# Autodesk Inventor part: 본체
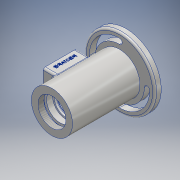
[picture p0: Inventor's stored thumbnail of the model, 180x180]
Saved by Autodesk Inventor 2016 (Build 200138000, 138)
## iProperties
Created: 2017-05
Part Number: 본체
Material: 알루미늄 6061
Document SubType Name: Modeling
Designer: USER
Density: 2.7 g/cm^3
Appearance: 알루미늄 - 평지
Mass: 673.236 g
Surface Area: 619.691 cm^2
Volume: 249.347 cm^3
Author: USER
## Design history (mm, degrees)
sketch "스케치1"
  geometry: C1 r 53 at (0, 0); 1 further point
  constraints: 1 centre point, 1 coincident
  dimensions: "d0" = 106 diameter of C1
extrude "돌출1" new body sketch "스케치1" distance "d1" = 10; taper "d2" = 0 deg
sketch "스케치2"
  geometry: C1 r 31 at (0, 0); 1 further point
  constraints: 1 centre point, 1 coincident
  dimensions: "d3" = 62 diameter of C1
extrude "돌출2" join sketch "스케치2" distance "d4" = 3; taper "d5" = 0 deg
sketch "스케치3"
  geometry: C1 r 31 at (0, 0); 1 further point
  constraints: 1 centre point, 1 coincident
  dimensions: "d6" = 62 diameter of C1
extrude "돌출3" join sketch "스케치3" distance "d7" = 102; taper "d8" = 0 deg
sketch "스케치4"
  geometry: L1 (0, 0)-(0, -177.717); L2 (-31, -112)-(31, -112) reference; L3 (-21, -112)-(-21, -103); L4 (-21, -103)-(-24, -103); L5 (-24, -103)-(-24, -100); L6 (-24, -100)-(-20, -100); L7 (-20, -100)-(-20, -91); L8 (-20, -91)-(-17.5, -91); L9 (-17.5, -91)-(-17.5, -87.75); L10 (-17.5, -87.75)-(-18.5, -87.75); L11 (-18.5, -87.75)-(-18.5, -86); L12 (-18.5, -86)-(-17.5, -86); L13 (31, 3)-(-31, 3) reference; L14 (-22.005, 3)-(-21.985, 3); L15 (-17.5, -75)-(-17.5, -86); L16 (0, 0)-(0, 7.987); L17 (-17.5, -75)-(-26, -75); L18 (-26, -75)-(-26, -37); L19 (-26, -37)-(-17.5, -37); L20 (-17.5, -37)-(-17.5, -26); L21 (-17.5, -26)-(-16.5, -26); L22 (-16.5, -26)-(-16.5, -21); L23 (-16.5, -21)-(-10, -21); L24 (-12.5, -11.7)-(-12.904, -11); L25 (-12.904, -11)-(-16, -11); L26 (-10, -21)-(-10, -18.3); L27 (-10, -18.3)-(-12.5, -18.3); L28 (-12.5, -18.3)-(-12.5, -11.7); L29 (-21, -112)-(0, -112); L30 (0, 3)-(-22, 3); L31 (0, -112)-(0, 3); L32 (-16, -11)-(-22, 3); 1 further point
  constraints: 60 end point, 14 perpendicular, 7 vertical, 6 point on line, 2 collinear, 2 horizontal, 2 midpoint, 1 horizontal alignment, 1 parallel
  dimensions: "d11" = 42 diameter of L3 L1; "d12" = 48 diameter of L5 L1; "d13" = 9 distance of L3.start L3.end; "d14" = 3 distance of L4.end L5.end; "d15" = 21 distance from line of L3.start L8; "d16" = 26 distance from line of L3.start L12; "d17" = 1.75 distance of L10.end L11.end; "d18" = 37 diameter of L11 L1; "d20" = 35 diameter of L9 L1; "d35" = 11 distance of L15.start L12.end; "d40" = 35 diameter of L15 L1; "d52" = 52 diameter of L18 L1; "d53" = 38 distance of L17.end L18.end; "d54" = 11 distance of L19.end L20.end; "d55" = 44 diameter of L30.end L16; "d57" = 0.7 vertical distance of L24.start L24.end; "d59" = 35 diameter of L20 L1; "d60" = 33 diameter of L22 L1; "d61" = 24 distance from line of L14.end L23; "d62" = 20 diameter of L26 L1; "d63" = 25 diameter of L28 L1; "d64" = 7.3 distance between parallel lines of L27 L25; "d65" = 2.7 distance of L23.end L26.end; "d115" = 20 distance between parallel lines of L31 L7; "d119" = 30 deg angle of L28 L24; "d120" = 32 diameter of L25.end L16
revolve "회전1" sketch "스케치4" stored, may be unused: angle "d66" = 90 deg
node "작업 평면1"
sketch "스케치5"
  geometry: L1 (-81, -20)-(-31, -20); L2 (-31, -20)-(-31, 20); L3 (-31, 20)-(-81, 20); L4 (-81, 20)-(-81, -20); L5 (-112, 31)-(-112, -31) reference; 2 further points
  constraints: 8 end point, 2 parallel, 1 horizontal, 1 horizontal alignment, 1 midpoint, 1 perpendicular
  dimensions: "d68" = 40 distance between parallel lines of L3 L1; "d69" = 50 distance of L1.start L1.end; "d70" = 31 distance between parallel lines of L5 L4
extrude "돌출4" join sketch "스케치5" stored distance "d71" = 102; taper "d72" = 0 deg
sketch "스케치6"
  geometry: L1 (-11, -72)-(11, -72); L2 (11, -72)-(11, -40); L3 (11, -40)-(-11, -40); L4 (-11, -40)-(-11, -72); L5 (-11, -56)-(11, -56); L6 (-31, -112)-(31, -112) reference; 2 further points
  constraints: 10 end point, 3 midpoint, 2 parallel, 1 horizontal, 1 perpendicular, 1 vertical alignment
  dimensions: "d73" = 32 distance of L3.end L1.start; "d74" = 22 distance of L2.end L3.end; "d75" = 56 distance from line of L6 L5.start
extrude "돌출5" cut sketch "스케치6" stored distance "d76" = 102; taper "d77" = 0 deg
sketch "스케치7"
  geometry: A1 r 41.5 centre (0, 0) between (41.5, 0) and (0, 41.5); A2 r 45.5 centre (0, 0) between (45.5, 0) and (0, 45.5); A3 r 37.5 centre (0, 0) between (37.5, 0) and (0, 37.5); A4 r 4 centre (41.5, 0) between (37.5, 0) and (45.5, 0); A5 r 4 centre (0, 41.5) between (0, 45.5) and (0, 37.5); A6 r 41.5 centre (0, 0) between (-41.5, 0) and (0, -41.5); A7 r 45.5 centre (0, 0) between (-45.5, 0) and (0, -45.5); A8 r 37.5 centre (0, 0) between (-37.5, 0) and (0, -37.5); A9 r 4 centre (-41.5, 0) between (-37.5, 0) and (-45.5, 0); A10 r 4 centre (0, -41.5) between (0, -45.5) and (0, -37.5); 1 further point
  constraints: 20 point on circle, 10 centre point, 8 tangent, 2 coincident, 2 horizontal alignment, 2 vertical alignment
  dimensions: "d78" = 45.5 radius of A2; "d79" = 37.5 radius of A3; "d80" = 37.5 radius of A8; "d81" = 45.5 radius of A7
extrude "돌출6" cut sketch "스케치7" stored distance "d82" = 0; taper "d83" = 0 deg
fillet "모깎기1" dims "d84" = 3
fillet "모깎기2" dims "d85" = 3
chamfer "모따기1" distance "d86" = 1; stored, may be unused: second distance "d87" = 2, angle "d88" = 45 deg
fillet "모깎기3" dims "d89" = 3
fillet "모깎기4" dims "d90" = 3
sketch "스케치8"
  geometry: L1 (-26, -75)-(26, -75) reference; L2 (17, -81)-(-17, -81) reference; L3 (-20, -78)-(-20, -34) reference; L4 (20, -34)-(20, -78) reference; L5 (-17, -31)-(17, -31) reference; 5 further points
  constraints: 2 horizontal alignment, 2 vertical alignment
  dimensions: "d92" = 4.5 distance from line of L2 point (-15.5, -76.5); "d93" = 4.5 distance from line of L3 point (-15.5, -76.5); "d94" = 4.5 distance from line of L4 point (15.5, -76.5); "d95" = 4.5 distance from line of L5 point (15.5, -35.5)
hole "구멍1" sketch "스케치8" at (-15.5, -35.5), (15.5, -35.5), (-15.5, -76.5), (15.5, -76.5) diameter "d96" = 2.459; stored, may be unused: countersink angle "d100" = 90 deg, drill point angle "d102" = 118 deg; dims "d97" = 6, "d98" = 4, "d99" = 2, "d101" = 8
fillet "모깎기5" dims "d103" = 0.3
fillet "모깎기6" dims "d104" = 3
chamfer "모따기2" distance "d105" = 1; stored, may be unused: second distance "d106" = 2, angle "d107" = 45 deg
fillet "모깎기7" dims "d108" = 3
feature "스레드1" dims "d109" = 10, "d110" = 0
sketch "스케치9"
  geometry: L1 (13, -34)-(75, -34) reference; L2 (0, 44)-(0, 0) reference; 2 further points
  constraints: 1 other
  dimensions: "d111" = 56 distance from line of L1 point (8, 22); "d112" = 8 distance from line of L2 point (8, 22)
feature "엠보싱1" sketch "스케치9" dims "d113" = 0.5, "d114" = 0
fillet "모깎기9" dims "d117" = 0.3
node "솔리드1"
other parameters: "d67" = -44
